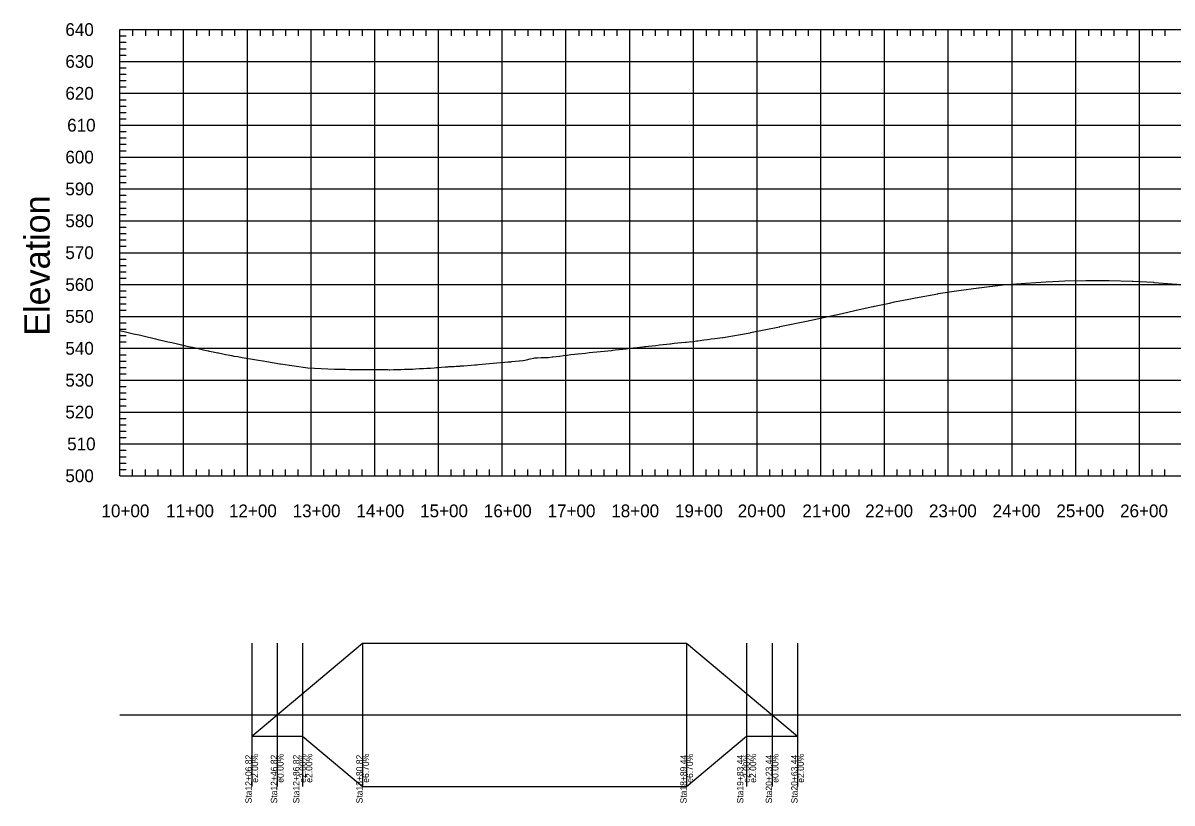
# Model space of a CAD drawing. Extents: x 708167 to 712470, y 374476 to 376945.
# Drawn here: x 708167 to 709970, y 374477 to 375700 of the extents above; entities that cross this region are included whole.
import ezdxf

# ---------------------------------------------------------------- set-up
doc = ezdxf.new("R2010")
doc.units = 0
for name, color, linetype in [('1', 7, 'Continuous'), ('54', 7, 'Continuous'), ('61', 7, 'Continuous'), ('Existing', 7, 'Continuous')]:
    doc.layers.add(name, color=color, linetype=linetype)

msp = doc.modelspace()

# ---------------------------------------------------------------- linework, layer by layer
for points in [[(708525.8, 374581.2), (708699.8, 374727.3), (709208.4, 374727.3), (709382.4, 374581.2)], [(708319, 374614.8), (712319, 374614.8)], [(708525.8, 374581.2), (708605.8, 374581.2), (708699.8, 374502.3), (709208.4, 374502.3), (709302.4, 374581.2), (709382.4, 374581.2)]]:
    msp.add_lwpolyline(points)
at = {"layer": '54'}
for points in [[(708525.8, 374727.3), (708525.8, 374502.3)], [(708565.8, 374727.3), (708565.8, 374502.3)], [(708605.8, 374727.3), (708605.8, 374502.3)], [(708699.8, 374727.3), (708699.8, 374502.3)], [(709208.4, 374727.3), (709208.4, 374502.3)], [(709302.4, 374727.3), (709302.4, 374502.3)], [(709342.4, 374727.3), (709342.4, 374502.3)], [(709382.4, 374727.3), (709382.4, 374502.3)]]:
    msp.add_lwpolyline(points, dxfattribs=at)
at = {"layer": '61'}
for p, q in [((708319, 375689.8), (712319, 375689.8)), ((708319, 374989.8), (708319, 375689.8)), ((708339, 375689.8), (708339, 375679.8)), ((708359, 375689.8), (708359, 375679.8)), ((708379, 375689.8), (708379, 375679.8)), ((708399, 375689.8), (708399, 375679.8)), ((708419, 374989.8), (708419, 375689.8)), ((708439, 375689.8), (708439, 375679.8)), ((708459, 375689.8), (708459, 375679.8)), ((708479, 375689.8), (708479, 375679.8)), ((708499, 375689.8), (708499, 375679.8)), ((708519, 374989.8), (708519, 375689.8)), ((708539, 375689.8), (708539, 375679.8)), ((708559, 375689.8), (708559, 375679.8)), ((708579, 375689.8), (708579, 375679.8)), ((708599, 375689.8), (708599, 375679.8)), ((708619, 374989.8), (708619, 375689.8)), ((708639, 375689.8), (708639, 375679.8)), ((708659, 375689.8), (708659, 375679.8)), ((708679, 375689.8), (708679, 375679.8)), ((708699, 375689.8), (708699, 375679.8)), ((708719, 374989.8), (708719, 375689.8)), ((708739, 375689.8), (708739, 375679.8)), ((708759, 375689.8), (708759, 375679.8)), ((708779, 375689.8), (708779, 375679.8)), ((708799, 375689.8), (708799, 375679.8)), ((708819, 374989.8), (708819, 375689.8)), ((708839, 375689.8), (708839, 375679.8)), ((708859, 375689.8), (708859, 375679.8)), ((708879, 375689.8), (708879, 375679.8)), ((708899, 375689.8), (708899, 375679.8)), ((708919, 374989.8), (708919, 375689.8)), ((708939, 375689.8), (708939, 375679.8)), ((708959, 375689.8), (708959, 375679.8)), ((708979, 375689.8), (708979, 375679.8)), ((708999, 375689.8), (708999, 375679.8)), ((709019, 374989.8), (709019, 375689.8)), ((709039, 375689.8), (709039, 375679.8)), ((709059, 375689.8), (709059, 375679.8)), ((709079, 375689.8), (709079, 375679.8)), ((709099, 375689.8), (709099, 375679.8)), ((709119, 374989.8), (709119, 375689.8)), ((709139, 375689.8), (709139, 375679.8)), ((709159, 375689.8), (709159, 375679.8)), ((709179, 375689.8), (709179, 375679.8)), ((709199, 375689.8), (709199, 375679.8)), ((709219, 374989.8), (709219, 375689.8)), ((709239, 375689.8), (709239, 375679.8)), ((709259, 375689.8), (709259, 375679.8)), ((709279, 375689.8), (709279, 375679.8)), ((709299, 375689.8), (709299, 375679.8)), ((709319, 374989.8), (709319, 375689.8)), ((709339, 375689.8), (709339, 375679.8)), ((709359, 375689.8), (709359, 375679.8)), ((709379, 375689.8), (709379, 375679.8)), ((709399, 375689.8), (709399, 375679.8)), ((709419, 374989.8), (709419, 375689.8)), ((709439, 375689.8), (709439, 375679.8)), ((709459, 375689.8), (709459, 375679.8)), ((709479, 375689.8), (709479, 375679.8)), ((709499, 375689.8), (709499, 375679.8)), ((709519, 374989.8), (709519, 375689.8)), ((709539, 375689.8), (709539, 375679.8)), ((709559, 375689.8), (709559, 375679.8)), ((709579, 375689.8), (709579, 375679.8)), ((709599, 375689.8), (709599, 375679.8)), ((709619, 374989.8), (709619, 375689.8)), ((709639, 375689.8), (709639, 375679.8)), ((709659, 375689.8), (709659, 375679.8)), ((709679, 375689.8), (709679, 375679.8)), ((709699, 375689.8), (709699, 375679.8)), ((709719, 374989.8), (709719, 375689.8)), ((709739, 375689.8), (709739, 375679.8)), ((709759, 375689.8), (709759, 375679.8)), ((709779, 375689.8), (709779, 375679.8)), ((709799, 375689.8), (709799, 375679.8)), ((709819, 374989.8), (709819, 375689.8)), ((709839, 375689.8), (709839, 375679.8)), ((709859, 375689.8), (709859, 375679.8)), ((709879, 375689.8), (709879, 375679.8)), ((709899, 375689.8), (709899, 375679.8)), ((709919, 374989.8), (709919, 375689.8)), ((709939, 375689.8), (709939, 375679.8)), ((709959, 375689.8), (709959, 375679.8)), ((708319, 375679.8), (708329, 375679.8)), ((708319, 375669.8), (708329, 375669.8)), ((708319, 375659.8), (708329, 375659.8)), ((708319, 375649.8), (708329, 375649.8)), ((708319, 375639.8), (712319, 375639.8)), ((708319, 375629.8), (708329, 375629.8)), ((708319, 375619.8), (708329, 375619.8)), ((708319, 375609.8), (708329, 375609.8)), ((708319, 375599.8), (708329, 375599.8)), ((708319, 375589.8), (712319, 375589.8)), ((708319, 375579.8), (708329, 375579.8)), ((708319, 375569.8), (708329, 375569.8)), ((708319, 375559.8), (708329, 375559.8)), ((708319, 375549.8), (708329, 375549.8)), ((708319, 375539.8), (712319, 375539.8)), ((708319, 375529.8), (708329, 375529.8)), ((708319, 375519.8), (708329, 375519.8)), ((708319, 375509.8), (708329, 375509.8)), ((708319, 375499.8), (708329, 375499.8)), ((708319, 375489.8), (712319, 375489.8)), ((708319, 375479.8), (708329, 375479.8)), ((708319, 375469.8), (708329, 375469.8)), ((708319, 375459.8), (708329, 375459.8)), ((708319, 375449.8), (708329, 375449.8)), ((708319, 375439.8), (712319, 375439.8)), ((708319, 375429.8), (708329, 375429.8)), ((708319, 375419.8), (708329, 375419.8)), ((708319, 375409.8), (708329, 375409.8)), ((708319, 375399.8), (708329, 375399.8)), ((708319, 375389.8), (712319, 375389.8)), ((708319, 375379.8), (708329, 375379.8)), ((708319, 375369.8), (708329, 375369.8)), ((708319, 375359.8), (708329, 375359.8)), ((708319, 375349.8), (708329, 375349.8)), ((708319, 375339.8), (712319, 375339.8)), ((708319, 375329.8), (708329, 375329.8)), ((708319, 375319.8), (708329, 375319.8)), ((708319, 375309.8), (708329, 375309.8)), ((708319, 375299.8), (708329, 375299.8)), ((708319, 375289.8), (712319, 375289.8)), ((708319, 375279.8), (708329, 375279.8)), ((708319, 375269.8), (708329, 375269.8)), ((708319, 375259.8), (708329, 375259.8)), ((708319, 375249.8), (708329, 375249.8)), ((708319, 375239.8), (712319, 375239.8)), ((708319, 375229.8), (708329, 375229.8)), ((708319, 375219.8), (708329, 375219.8)), ((708319, 375209.8), (708329, 375209.8)), ((708319, 375199.8), (708329, 375199.8)), ((708319, 375189.8), (712319, 375189.8)), ((708319, 375179.8), (708329, 375179.8)), ((708319, 375169.8), (708329, 375169.8)), ((708319, 375159.8), (708329, 375159.8)), ((708319, 375149.8), (708329, 375149.8)), ((708319, 375139.8), (712319, 375139.8)), ((708319, 375129.8), (708329, 375129.8)), ((708319, 375119.8), (708329, 375119.8)), ((708319, 375109.8), (708329, 375109.8)), ((708319, 375099.8), (708329, 375099.8)), ((708319, 375089.8), (712319, 375089.8)), ((708319, 375079.8), (708329, 375079.8)), ((708319, 375069.8), (708329, 375069.8)), ((708319, 375059.8), (708329, 375059.8)), ((708319, 375049.8), (708329, 375049.8)), ((708319, 375039.8), (712319, 375039.8)), ((708319, 375029.8), (708329, 375029.8)), ((708319, 375019.8), (708329, 375019.8)), ((708319, 375009.8), (708329, 375009.8)), ((708319, 374999.8), (708329, 374999.8)), ((708319, 374989.8), (712319, 374989.8)), ((708339, 374989.8), (708339, 374999.8)), ((708359, 374989.8), (708359, 374999.8)), ((708379, 374989.8), (708379, 374999.8)), ((708399, 374989.8), (708399, 374999.8)), ((708439, 374989.8), (708439, 374999.8)), ((708459, 374989.8), (708459, 374999.8)), ((708479, 374989.8), (708479, 374999.8)), ((708499, 374989.8), (708499, 374999.8)), ((708539, 374989.8), (708539, 374999.8)), ((708559, 374989.8), (708559, 374999.8)), ((708579, 374989.8), (708579, 374999.8)), ((708599, 374989.8), (708599, 374999.8)), ((708639, 374989.8), (708639, 374999.8)), ((708659, 374989.8), (708659, 374999.8)), ((708679, 374989.8), (708679, 374999.8)), ((708699, 374989.8), (708699, 374999.8)), ((708739, 374989.8), (708739, 374999.8)), ((708759, 374989.8), (708759, 374999.8)), ((708779, 374989.8), (708779, 374999.8)), ((708799, 374989.8), (708799, 374999.8)), ((708839, 374989.8), (708839, 374999.8)), ((708859, 374989.8), (708859, 374999.8)), ((708879, 374989.8), (708879, 374999.8)), ((708899, 374989.8), (708899, 374999.8)), ((708939, 374989.8), (708939, 374999.8)), ((708959, 374989.8), (708959, 374999.8)), ((708979, 374989.8), (708979, 374999.8)), ((708999, 374989.8), (708999, 374999.8)), ((709039, 374989.8), (709039, 374999.8)), ((709059, 374989.8), (709059, 374999.8)), ((709079, 374989.8), (709079, 374999.8)), ((709099, 374989.8), (709099, 374999.8)), ((709139, 374989.8), (709139, 374999.8)), ((709159, 374989.8), (709159, 374999.8)), ((709179, 374989.8), (709179, 374999.8)), ((709199, 374989.8), (709199, 374999.8)), ((709239, 374989.8), (709239, 374999.8)), ((709259, 374989.8), (709259, 374999.8)), ((709279, 374989.8), (709279, 374999.8)), ((709299, 374989.8), (709299, 374999.8)), ((709339, 374989.8), (709339, 374999.8)), ((709359, 374989.8), (709359, 374999.8)), ((709379, 374989.8), (709379, 374999.8)), ((709399, 374989.8), (709399, 374999.8)), ((709439, 374989.8), (709439, 374999.8)), ((709459, 374989.8), (709459, 374999.8)), ((709479, 374989.8), (709479, 374999.8)), ((709499, 374989.8), (709499, 374999.8)), ((709539, 374989.8), (709539, 374999.8)), ((709559, 374989.8), (709559, 374999.8)), ((709579, 374989.8), (709579, 374999.8)), ((709599, 374989.8), (709599, 374999.8)), ((709639, 374989.8), (709639, 374999.8)), ((709659, 374989.8), (709659, 374999.8)), ((709679, 374989.8), (709679, 374999.8)), ((709699, 374989.8), (709699, 374999.8)), ((709739, 374989.8), (709739, 374999.8)), ((709759, 374989.8), (709759, 374999.8)), ((709779, 374989.8), (709779, 374999.8)), ((709799, 374989.8), (709799, 374999.8)), ((709839, 374989.8), (709839, 374999.8)), ((709859, 374989.8), (709859, 374999.8)), ((709879, 374989.8), (709879, 374999.8)), ((709899, 374989.8), (709899, 374999.8)), ((709939, 374989.8), (709939, 374999.8)), ((709959, 374989.8), (709959, 374999.8))]:
    msp.add_line(p, q, dxfattribs=at)
at = {"layer": 'Existing'}
msp.add_lwpolyline([(708319, 375217.7), (708329.6, 375215.2), (708336.1, 375213.7), (708342.5, 375212.2), (708342.7, 375212.1), (708342.8, 375212.1), (708342.8, 375212.1), (708349, 375210.7), (708355.4, 375209.2), (708355.5, 375209.2), (708355.5, 375209.2), (708361.9, 375207.7), (708368.4, 375206.2), (708374.9, 375204.6), (708378.5, 375203.8), (708378.6, 375203.8), (708378.7, 375203.7), (708381.3, 375203.1), (708387.8, 375201.7), (708394.3, 375200.2), (708400.7, 375198.7), (708407.2, 375197.2), (708413.7, 375195.7), (708415.8, 375195.2), (708416, 375195.2), (708416.1, 375195.2), (708416.1, 375195.2), (708416.2, 375195.1), (708420.2, 375194.3), (708426.6, 375192.8), (708433.1, 375191.4), (708439.6, 375189.9), (708446, 375188.5), (708452.5, 375187), (708457.4, 375185.9), (708457.5, 375185.9), (708458, 375185.7), (708458, 375185.7), (708458.1, 375185.7), (708459, 375185.5), (708465.4, 375184.2), (708471.9, 375182.9), (708473.9, 375182.5), (708478.4, 375181.6), (708484.8, 375180.2), (708491.3, 375178.9), (708494, 375178.3), (708494, 375178.3), (708494.1, 375178.3), (708494.4, 375178.3), (708497.8, 375177.7), (708504.3, 375176.7), (708510.7, 375175.6), (708517.2, 375174.5), (708523.7, 375173.5), (708530.1, 375172.4), (708533.2, 375171.9), (708533.4, 375171.8), (708536.6, 375171.3), (708543.1, 375170.1), (708543.6, 375170.1), (708549.5, 375169), (708569.9, 375165.4), (708570.6, 375165.3), (708570.6, 375165.3), (708570.7, 375165.3), (708570.7, 375165.3), (708571, 375165.2), (708614, 375159.1), (708655.6, 375157.2), (708656.2, 375157.1), (708656.2, 375157.1), (708656.2, 375157.1), (708656.2, 375157.1), (708661.4, 375157.1), (708667.2, 375157), (708673, 375156.9), (708678.8, 375156.8), (708684.6, 375156.7), (708690.4, 375156.6), (708694.3, 375156.5), (708694.3, 375156.5), (708695.8, 375156.5), (708696.2, 375156.5), (708702, 375156.5), (708707.8, 375156.5), (708713.6, 375156.5), (708719.4, 375156.4), (708725.2, 375156.4), (708731, 375156.4), (708736.8, 375156.3), (708739.1, 375156.3), (708739.2, 375156.3), (708741.3, 375156), (708742.3, 375156), (708742.6, 375156), (708748.4, 375156.3), (708750.8, 375156.5), (708754.1, 375156.6), (708759.9, 375156.8), (708765.7, 375157), (708771.5, 375157.1), (708777.3, 375157.3), (708778.9, 375157.3), (708783.1, 375157.6), (708788.9, 375157.9), (708794.7, 375158.2), (708795.2, 375158.2), (708800.5, 375158.5), (708806.3, 375158.9), (708812.1, 375159.3), (708815.8, 375159.5), (708817.9, 375159.7), (708823.7, 375160.2), (708829.5, 375160.7), (708833.6, 375161), (708835.3, 375161.1), (708841.1, 375161.3), (708843.8, 375161.4), (708846.9, 375161.6), (708852.7, 375162), (708853.4, 375162.1), (708858.5, 375162.4), (708864.3, 375162.9), (708870.1, 375163.3), (708875.9, 375163.7), (708878.6, 375163.9), (708881.7, 375164.2), (708887.5, 375164.7), (708893.3, 375165.3), (708899.1, 375165.8), (708904.9, 375166.3), (708910.7, 375166.8), (708916.5, 375167.3), (708922.3, 375167.8), (708922.9, 375167.9), (708928, 375168.4), (708932.6, 375168.8), (708933.8, 375168.9), (708939.6, 375169.4), (708945.4, 375169.9), (708946.2, 375170), (708951.2, 375170.5), (708951.6, 375170.6), (708957, 375171.8), (708962.8, 375173.2), (708968.6, 375174.5), (708970.2, 375174.9), (708974.4, 375175), (708980.2, 375175.2), (708986, 375175.3), (708991, 375175.5), (708991.8, 375175.6), (708997.6, 375176.2), (708998.5, 375176.3), (709003.4, 375177), (709009.2, 375177.7), (709015, 375178.5), (709020.8, 375179.2), (709026.6, 375179.9), (709026.9, 375180), (709032.4, 375180.5), (709037.4, 375181), (709038.2, 375181.1), (709044, 375181.8), (709049.8, 375182.4), (709055.6, 375183), (709061.1, 375183.6), (709061.4, 375183.6), (709067.2, 375184.2), (709073, 375184.8), (709078.8, 375185.4), (709084.6, 375186), (709090.4, 375186.6), (709092.7, 375186.8), (709096.2, 375187.2), (709102, 375187.8), (709106.7, 375188.2), (709107.7, 375188.5), (709108.2, 375188.6), (709113.5, 375189.2), (709119.3, 375189.9), (709125.1, 375190.5), (709130.9, 375191.1), (709134.5, 375191.5), (709136.7, 375191.8), (709142.5, 375192.4), (709144.5, 375192.6), (709148.3, 375193), (709154.1, 375193.7), (709159.9, 375194.3), (709165.7, 375195), (709171.5, 375195.6), (709177.3, 375196.2), (709182.2, 375196.8), (709183.1, 375196.9), (709185.5, 375197.1), (709185.5, 375197.3), (709185.6, 375197.4), (709188.9, 375197.8), (709194.7, 375198.3), (709200.5, 375198.9), (709206.3, 375199.5), (709207.6, 375199.6), (709212.1, 375200.1), (709217.9, 375200.7), (709223.7, 375201.3), (709224.7, 375201.4), (709225.7, 375201.5), (709229.5, 375202.1), (709235.3, 375202.9), (709241.1, 375203.7), (709246.9, 375204.5), (709252.7, 375205.3), (709264.9, 375206.9), (709265.5, 375207), (709308, 375214.3), (709308.7, 375214.4), (709354.3, 375223.7), (709354.4, 375223.7), (709354.4, 375223.8), (709354.5, 375223.8), (709396.7, 375232.5), (709442.6, 375242.3), (709442.8, 375242.3), (709454.8, 375245), (709479.3, 375250.5), (709500.4, 375255.3), (709500.6, 375255.3), (709501.7, 375255.5), (709503.2, 375255.7), (709503.3, 375255.7), (709526.5, 375260.8), (709534.5, 375262.5), (709534.6, 375262.6), (709556.9, 375266.9), (709567.5, 375269), (709567.5, 375269), (709602.8, 375275.5), (709602.9, 375275.6), (709635.3, 375280.4), (709635.4, 375280.4), (709635.4, 375280.4), (709635.5, 375280.4), (709635.5, 375280.4), (709666.6, 375284.8), (709666.7, 375284.9), (709666.7, 375284.9), (709666.7, 375284.9), (709705.1, 375289.2), (709740, 375292), (709740.4, 375292), (709772.4, 375294), (709783, 375294.6), (709801.8, 375295.6), (709834.9, 375296.2), (709835.7, 375296.3), (709870.2, 375296.1), (709871.3, 375296), (709907.4, 375295.2), (709908.4, 375295.1), (709909.3, 375295.1), (709940.9, 375293.3), (709941.7, 375293.2), (709977.7, 375290.3)], dxfattribs=at)

# ---------------------------------------------------------------- texts
msp.add_text(' Superelevation: ', height=0.14).set_placement((708299, 374614.7))
at = {"layer": '1'}
msp.add_text('Elevation', height=40, rotation=90, dxfattribs=at).set_placement((708209, 375209.6))
at = {"layer": '54'}
for s, p in [('e2.00%', (708535.9, 374508.3)), ('e0.00%', (708575.9, 374508.3)), ('e2.00%', (708610.8, 374508.3)), ('e2.00%', (708620.9, 374508.3)), ('e6.70%', (708709.9, 374508.3)), ('Sta18+89.44', (709208.4, 374475.9)), ('e6.70%', (709218.5, 374508.3)), ('Sta19+83.44', (709297.4, 374475.9)), ('e2.00%', (709307.4, 374508.3)), ('e2.00%', (709317.5, 374508.3)), ('Sta20+23.44', (709342.4, 374475.9)), ('e0.00%', (709352.5, 374508.3)), ('Sta20+63.44', (709382.4, 374475.9)), ('e2.00%', (709392.5, 374508.3)), ('Sta12+06.82', (708525.8, 374476)), ('Sta12+46.82', (708565.8, 374476)), ('Sta12+86.82', (708600.7, 374476)), ('Sta13+80.82', (708699.8, 374476))]:
    msp.add_text(s, height=10, rotation=90, dxfattribs=at).set_placement(p)
at = {"layer": '61'}
for s, p in [('640', (708233.4, 375679.8)), ('640', (708233.4, 375679.8)), ('630', (708233.4, 375629.8)), ('620', (708233.4, 375579.8)), ('610', (708236.2, 375529.8)), ('600', (708233.4, 375479.8)), ('590', (708233.4, 375429.8)), ('580', (708233.4, 375379.8)), ('570', (708233.4, 375329.8)), ('560', (708233.4, 375279.8)), ('550', (708233.4, 375229.8)), ('540', (708233.4, 375179.8)), ('530', (708233.4, 375129.8)), ('520', (708233.4, 375079.8)), ('510', (708236.2, 375029.8)), ('500', (708233.4, 374979.8)), ('10+00', (708290.1, 374924.8)), ('11+00', (708391.5, 374924.8)), ('12+00', (708490.1, 374924.8)), ('13+00', (708590.1, 374924.8)), ('14+00', (708690.1, 374924.8)), ('15+00', (708790.1, 374924.8)), ('16+00', (708890.1, 374924.8)), ('17+00', (708990.1, 374924.8)), ('18+00', (709090.1, 374924.8)), ('19+00', (709190.1, 374924.8)), ('20+00', (709288.6, 374924.8)), ('21+00', (709390.1, 374924.8)), ('22+00', (709488.6, 374924.8)), ('23+00', (709588.6, 374924.8)), ('24+00', (709688.6, 374924.8)), ('25+00', (709788.6, 374924.8)), ('26+00', (709888.6, 374924.8))]:
    msp.add_text(s, height=20, dxfattribs=at).set_placement(p)

doc.saveas('drawing.dxf')
